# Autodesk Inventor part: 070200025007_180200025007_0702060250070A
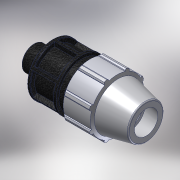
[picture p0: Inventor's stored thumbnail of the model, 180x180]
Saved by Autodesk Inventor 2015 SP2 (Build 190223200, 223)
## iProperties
Created: 2017-02
Part Number: 070200025007_180200025007_0702060250070A
Material: PVC-Piping
Description: PLASSON MALE ADAPTOR 25-3/4"
Document SubType Name: Modeling
Designer: KIM
Mass: 92.6774 g
Surface Area: 199.44 cm^2
Volume: 66.1981 cm^3
Density: 1.4 g/cm^3
Appearance: PTFE
Author: KIM
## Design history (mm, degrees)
derived "07020.ipt"
feature "Solid1::07020.ipt"
tag "TaggingFeature1"
body "Solid1"
other parameters: "d2" = 25, "d4" = 13.57143, "d5" = 23.75, "d7" = 54, "d8" = 40.5, "d9" = 13.57143, "d11" = 2.71429, "d12" = 43.2, "d13" = 120 deg, "d14" = 37.5, "d15" = 12 deg, "d16" = 48.6, "d18" = 1.25, "d19" = 35 deg, "d20" = 17.5 deg, "d21" = 50.22, "d23" = 0, "d25" = 360 deg, "d27" = 1.08, "d34" = 2.7, "d36" = 0, "d42" = 23.75, "d43" = 1.62, "d46" = 0.75, "d49" = 72, "d51" = 95, "d52" = 18, "d53" = 0.5, "d55" = 360 deg, "d57" = 26.441, "d58" = 18.5087, "d59" = 19, "d_" = 25, "E_" = 54, "H_" = 95, "l_" = 72, "l_2" = 18, "R_" = 26.441
